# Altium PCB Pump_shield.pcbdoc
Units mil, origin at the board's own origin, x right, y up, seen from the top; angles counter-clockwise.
Board outline 6300 x 3950 mil, 3 copper layers (Top Layer, Mid-Layer 1, Bottom Layer); 32 components, 23 nets, 98 pads, 0 vias.
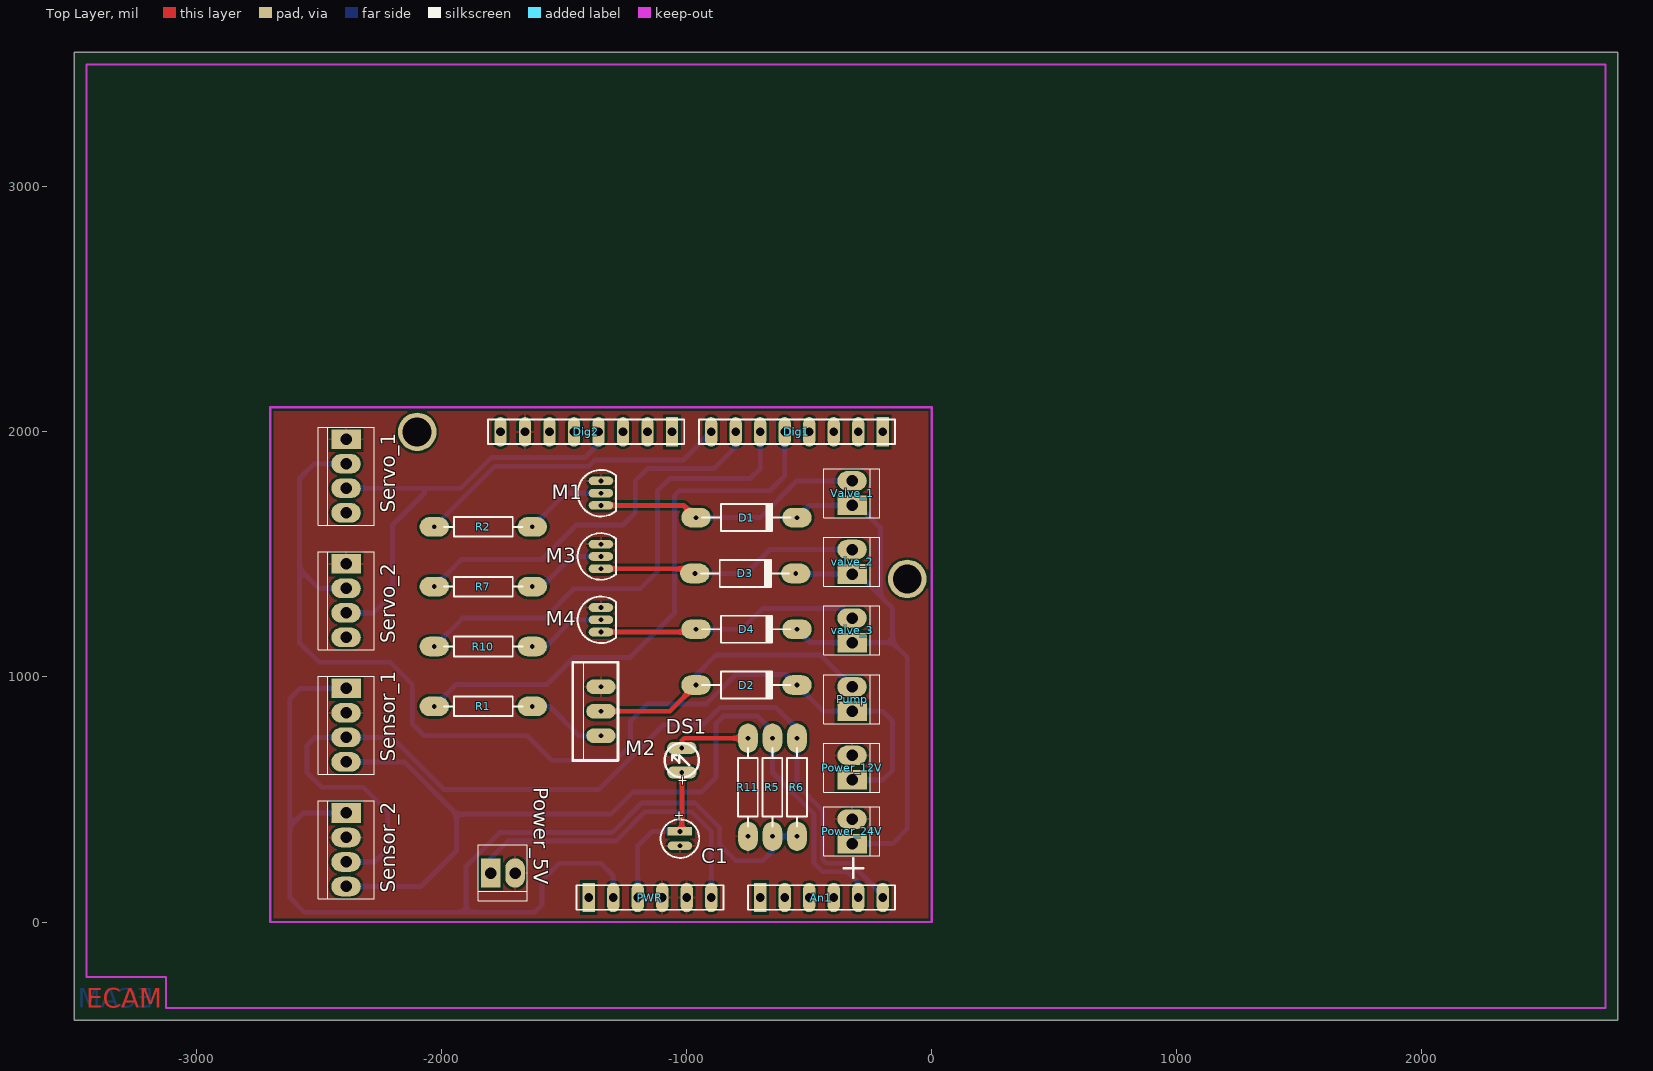
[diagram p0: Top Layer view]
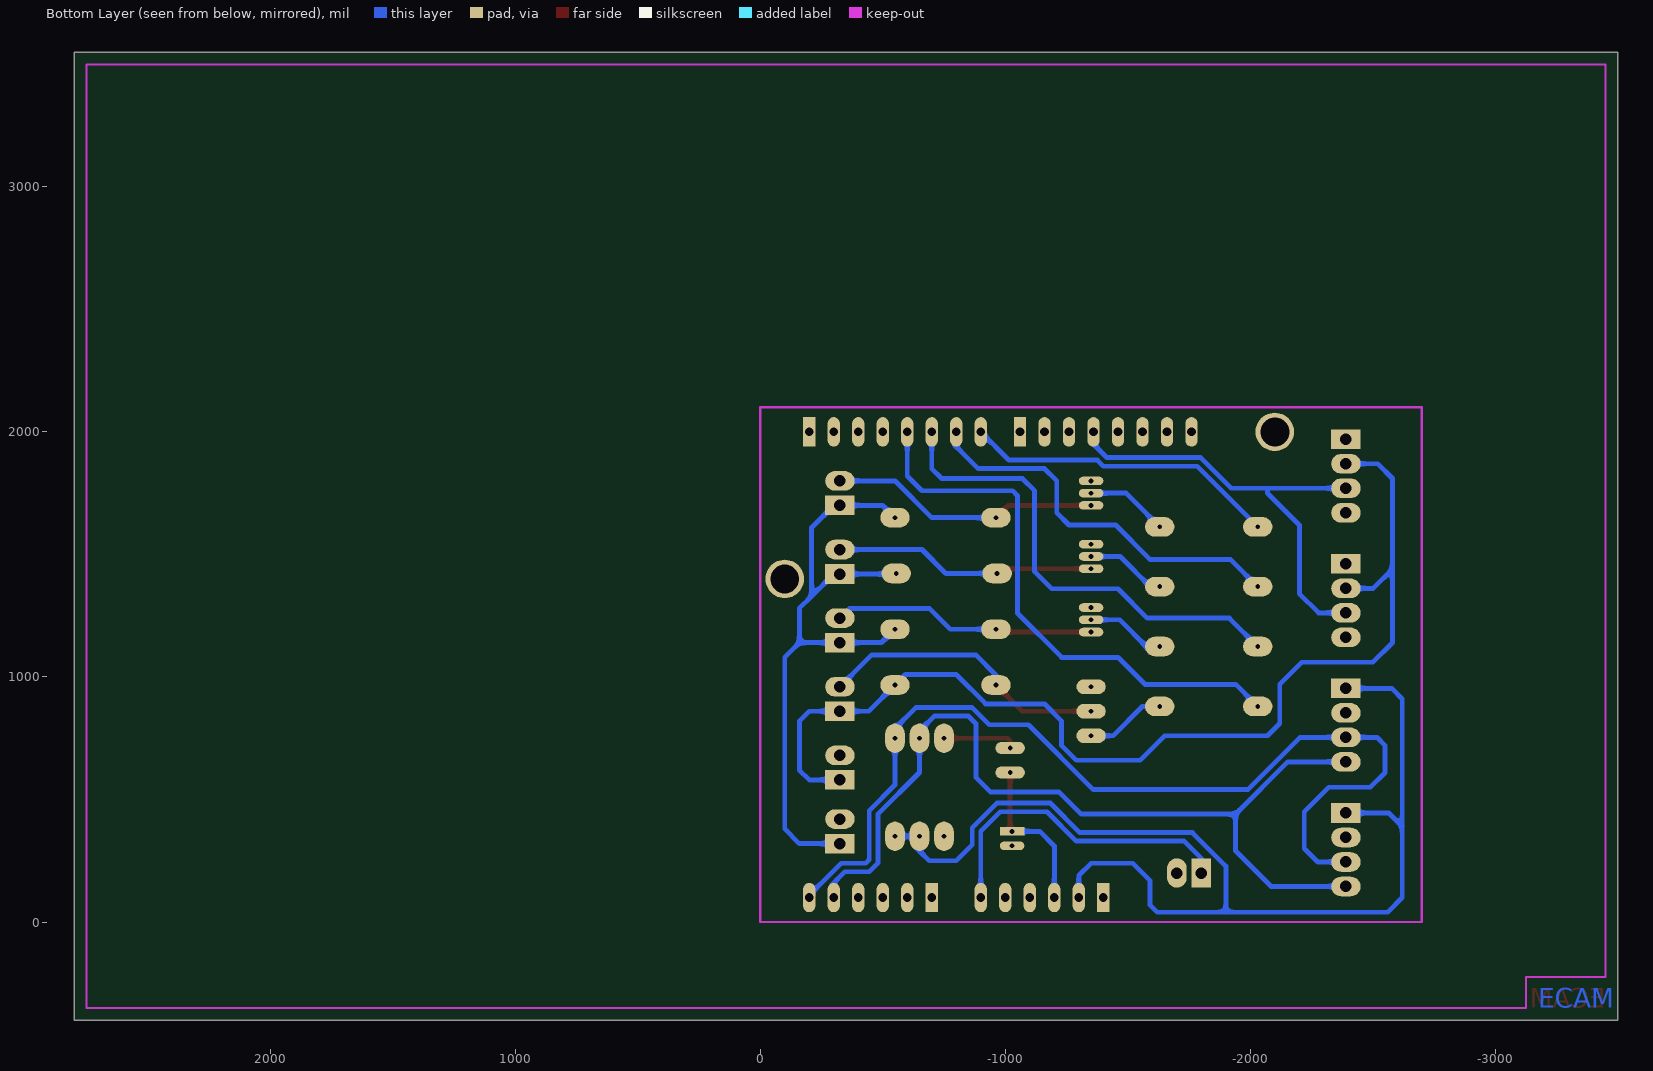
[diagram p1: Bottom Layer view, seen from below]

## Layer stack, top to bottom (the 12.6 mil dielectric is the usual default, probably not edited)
Top Solder: solder mask 0.4, Solder Resist, Dk 3.5
Top Layer: signal copper 1.4
Dielectric1: core 12.6, FR-4, Dk 4.8
Mid-Layer 1: signal copper 1.4
Dielectric2: dielectric 12.6, FR-4, Dk 4.8
Bottom Layer: signal copper 1.4
Bottom Solder: solder mask 0.4, Solder Resist, Dk 3.5

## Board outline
-3500,-400 -3500,3550 2800,3550 2800,-400

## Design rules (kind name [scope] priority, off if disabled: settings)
Clearance "Clearance T DIP" [(IsTrack) vs (IsPad AND( HasFootprint('DIP*')))] p1: gap=10 ignorepadtopadclearanceinfootprint=FALSE
Clearance "Clearance PT" [(isTrack) vs (isPad)] p2: gap=10 ignorepadtopadclearanceinfootprint=FALSE
Clearance "Clearance TT" [(isTrack) vs (isTrack)] p3: gap=15 ignorepadtopadclearanceinfootprint=FALSE
Clearance "Clearance PP" [(IsPad) vs (IsPad)] p4: gap=10 ignorepadtopadclearanceinfootprint=FALSE
Clearance [All] p5: gap=10 ignorepadtopadclearanceinfootprint=FALSE
FabricationTestPointUsage TestPointUsage [All] p1: valid=0 allowmultiple=FALSE
FabricationTestpoint Testpoint [All] p1: side=3 testpointundercomponent=TRUE minsize=40 maxsize=100 preferedsize=60 minholesize=0 maxholesize=40 preferedholesize=32 testpointgrid=1 allowsidetop=TRUE allowsidebottom=TRUE usegrid=TRUE gridtolerance=0.01
HoleSize [All] p1: absolutevalues=TRUE maxlimit=21.65 minlimit=17.72 maxpercent=80.000 minpercent=20.000
PlaneClearance [All] p1: clearance=10
PlaneConnect [All] p1: planeconnectstyle=Relief reliefexpansion=10 reliefentries=4 reliefconductorwidth=10 reliefairgap=5
PolygonConnect [All] p1: connectstyle=Relief reliefconductorwidth=10 reliefentries=4 polygonreliefangle="90 Angle" airgapwidth=10
RoutingCorners [All] p1: cornerstyle=45-Degree minsetback=100 maxsetback=1000
RoutingLayers [All] p1: top layer_v5=TRUE mid layer 1_v5=FALSE bottom layer_v5=TRUE
RoutingVias "ECAM Vias" [All] p1: holewidth=19.68 width=80 viastyle="Through Hole" minholewidth=17.72 minwidth=60 maxholewidth=21.65 maxwidth=120
SolderMaskExpansion [All] p1: expansion=4
UnpouredPolygon [InNet('3V3')] p1:
Width Width_GND [InNet('GND')] p1: maxlimit=40 minlimit=10 preferedwidth=20
Width Width_VCC [InNet('VCC')] p2: maxlimit=40 minlimit=10 preferedwidth=20
Width [All] p3: maxlimit=40 minlimit=10 preferedwidth=20
22 further rules are at their usual default settings.

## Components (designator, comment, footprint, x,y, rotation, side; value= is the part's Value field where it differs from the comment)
An1 "Header 6" HDR1X6 -700,100 r0 top
C1 "Cond pol radial" CAPPR1.5-4x5 -1027.68,370 r270 top
D1 "Diode" DIO10.46-5.3x2.8 -961.81,1650 r0 top
D2 "Diode" DIO10.46-5.3x2.8 -961.81,967.19 r0 top
D3 "Diode" DIO10.46-5.3x2.8 -966.81,1422.4 r0 top
D4 "Diode" DIO10.46-5.3x2.8 -961.81,1194.79 r0 top
Dig1 "Header 8" HDR1X8 -200,2000 r180 top
Dig2 "Header 8" HDR1X8 -1060,2000 r180 top
DS1 "LED" "LED 0.1" -1020,610 r90 top
M1 "MOSFET-N" TO-92 -1350,1800 r0 top value=NMOS
M2 "MOSFET-N" "TO-220 V" -1350,760 r90 top value=NMOS
M3 "MOSFET-N" TO-92 -1350,1541.67 r0 top value=NMOS
M4 "MOSFET-N" TO-92 -1350,1283.33 r0 top value=NMOS
Power_5V "Molex_2" Header_2Ecam -1650,200.79 r180 top
Power_12V "Molex_2" Header_2Ecam -325.79,730 r270 top
Power_24V "Molex_2" Header_2Ecam -325.79,470 r270 top
Pump "Molex_2" Header_2Ecam -325.79,1010 r270 top
PWR "Header 6" HDR1X6 -1400,100 r0 top
R1 "Résistance" AXIAL-0.4 -2030,880 r0 top
R2 "Résistance" AXIAL-0.4 -2030,1612.81 r0 top
R5 "Résistance" AXIAL-0.4 -650,750 r270 top
R6 "Résistance" AXIAL-0.4 -550,750 r270 top
R7 "Résistance" AXIAL-0.4 -2030,1368.54 r0 top
R10 "Résistance" AXIAL-0.4 -2030,1124.27 r0 top
R11 "Résistance" AXIAL-0.4 -750,350 r90 top
Sensor_1 "Molex_4" Header4_ecam -2389.21,603.33 r90 top
Sensor_2 "Molex_4" Header4_ecam -2389.21,95 r90 top
Servo_1 "Molex_4" Header4_ecam -2389.21,1620 r90 top
Servo_2 "Molex_4" Header4_ecam -2389.21,1111.67 r90 top
Valve_1 "Molex_2" Header_2Ecam -325.79,1850 r270 top
valve_2 "Molex_2" Header_2Ecam -325.79,1570 r270 top
valve_3 "Molex_2" Header_2Ecam -325.79,1290 r270 top

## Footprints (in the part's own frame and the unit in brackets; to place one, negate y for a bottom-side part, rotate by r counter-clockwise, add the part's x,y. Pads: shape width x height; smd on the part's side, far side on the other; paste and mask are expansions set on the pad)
AXIAL-0.4 [mil] "Resistor; 2 Leads"
  oval 120x80 hole 19.68: 1(0,0) 2(400,0)
  silkscreen extent 40,-40 360,40
CAPPR1.5-4x5 [mm] "Capacitor, Electrolytic, Radial; Body 4 x 5 mm (Dia.xH typ); Pin Spacing 1.5 mm (typ)"
  rect 0.889x2.54 hole 0.5: 1(0,0)
  oval 0.889x2.54 hole 0.5: 2(1.5,0)
  silkscreen extent -1.25,-2 2.75,2
DIO10.46-5.3x2.8 [mil] "Diode, Axial; Body 5.2 x 2.7 mm (LxDia. max), Lead Dia. 0.86 mm (max)"
  oval 120x80 hole 19.68: 1(0,0) 2(411.81,0)
  silkscreen extent 25,-55 385,55
HDR1X6 [mil] "Connector; Header; 6 Position"
  rect 50x120 hole 35.43: 1(0,0)
  oval 50x120 hole 35.43: 2(100,0) 3(200,0) 4(300,0) 5(400,0) 6(500,0)
  silkscreen extent -50,-50 550,50
HDR1X8 [mil] "Connector; Header; 8 Position"
  rect 50x120 hole 35.43: 1(0,0)
  oval 50x120 hole 35.43: 2(100,0) 3(200,0) 4(300,0) 5(400,0) 6(500,0) 7(600,0) 8(700,0)
  silkscreen extent -50,-50 750,50
Header4_ecam [mil]
  rect 80x120 hole 46.85: 1(350,0.79)
  oval 80x120 hole 46.85: 2(250,0.79) 3(150,0.79) 4(50,0.79)
  silkscreen extent 0,-114 400,114
Header_2Ecam [mil]
  rect 80x120 hole 46.85: 1(150,0.79)
  oval 80x120 hole 46.85: 2(50,0.79)
  silkscreen extent 0,-114 200,114
"LED 0.1" [mil] "Led Verticale"
  oval 50x120 hole 19.68: 1(0,0) 2(100,0)
  silkscreen extent -20,-70 120,70
TO-92 [mil] "TO, Flat Index; 3 In-Line, Axial Leads; Body Dia. 4.6mm; Leads 0.48 x 0.43 mm (max) NOT ECAM RULES"
  oval 100x35 hole 19.68: D(0,-100) G(0,-50) S(0,0)
  silkscreen extent -95,-145 61,45
"TO-220 V" [mil] "TO-220 Vertical"
  oval 60x120 hole 19.68: D(100,0) G(0,0) S(200,0)
  silkscreen extent -100,-70 300,115

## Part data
An1 PWR: "Header, 6-Pin"
C1: "Condensateur polatisé"
Dig1 Dig2: "Header, 8-Pin"
DS1: Color=Rouge
M1 M2 M3 M4: "MOSFET"
Power_5V Power_12V Power_24V Pump Valve_1 valve_2 valve_3: "Header, 2-pin"
R1 R2 R5 R6 R7 R10 R11: "Résistance standard"
Sensor_1 Sensor_2 Servo_1 Servo_2: "Header, 4-Pin"

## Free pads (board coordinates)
  round 157.48 hole 118.11: M(-2100,2000) M(-100,1400)

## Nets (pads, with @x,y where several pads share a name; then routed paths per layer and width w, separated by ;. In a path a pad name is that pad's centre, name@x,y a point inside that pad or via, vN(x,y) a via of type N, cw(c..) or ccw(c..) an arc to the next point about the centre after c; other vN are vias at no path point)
3V3: PWR.2 R5.2 R6.2 Sensor_1.1 Sensor_2.1 | length 4767
  Bottom Layer w20: Sensor_2.1 -2565,445 -2620,390 ; Sensor_1.1 -2576.67,953.33 -2620,910 -2620,390 ; PWR.2 -1300,190 -1350,240 -1520,240 -1590,170 -1590,70 -1620,40 -1900,40 ; R6.2 R5.2 -650,290 -690,250 -800,250 -865,315 -865,384.5 -965.5,485 -1184.5,485 -1304.5,365 -1763.28,365 -1900,228.28 -1900,40 ; -2620,390 -2620,100 -2560,40 -1900,40
+5: Power_5V.1 PWR.6 | length 1341.8
  Bottom Layer w20: Power_5V.1 -1800,260 -1730,330 -1290,330 -1170,450 -980,450 -900,370 PWR.6
+12: D2.2 Power_12V.1 Pump.1 Servo_1.2 Servo_2.2 | length 4483.7
  Bottom Layer w20: Servo_2.2 -2501.67,1361.67 -2580,1440 ; Servo_1.2 -2520,1870 -2580,1810 -2580,1440 ; Power_12V.1 -200,580 -160,620 -160,820 -200,860 Pump.1 -442.81,860 D2.2 -592.81,1010 -800,1010 -920,890 -1160,890 -1230,820 -1230,720 -1290,660 -1550,660 -1650,760 -2070,760 -2120,810 -2120,970 -2210,1060 -2500,1060 -2580,1140 -2580,1440
+24: D1.2 D3.2 D4.2 Power_24V.1 Valve_1.1 valve_2.1 valve_3.1 | length 2719.4
  Bottom Layer w20: D3.2 -552.6,1420 valve_2.1 -300,1420 -210,1330 ; D4.2 -495.21,1140 valve_3.1 -160,1140 ; D1.2 -500,1700 Valve_1.1 -300,1700 -210,1610 -210,1330 ; Power_24V.1 -160,320 -100,380 -100,1080 -160,1140 ; -210,1330 -160,1280 -160,1140
GND: C1.2 Dig2.7 M1.S M2.S M3.S M4.S Power_5V.2 Power_12V.2 Power_24V.2 PWR.4 PWR.5 R11.1 Sensor_1.2 Sensor_2.2 Servo_1.1 Servo_2.1
NetDS1_2: DS1.2 R11.2 | length 304.1
  Top Layer w20: DS1.2 -1020,740 -1010,750 R11.2
NetM1_G: M1.G R2.2 | length 336.8
  Bottom Layer w20: R2.2 -1492.81,1750 M1.G
NetM2_G: M2.G R1.2 | length 329.7
  Bottom Layer w20: R1.2 -1560,880 -1440,760 M2.G
NetM3_G: M3.G R7.2 | length 331
  Bottom Layer w20: R7.2 -1591.46,1368.54 -1468.33,1491.67 M3.G
NetM4_G: M4.G R10.2 | length 325.2
  Bottom Layer w20: R10.2 -1575.73,1124.27 -1466.67,1233.33 M4.G
Pump: Dig1.5 R1.1 | length 2280.5
  Bottom Layer w20: R1.1 -1940,970 -1570,970 -1460,1080 -1230,1080 -1050,1260 -1050,1740 -1030,1760 -660,1760 -600,1820 Dig1.5
RX_moteur: Dig2.3
SCL_Sensor: An1.6 R6.1 Sensor_1.3 Sensor_2.3 | length 4018.5
  Bottom Layer w20: Sensor_2.3 -2275,245 -2220,300 -2220,450 -2320,550 -2490,550 -2550,610 -2550,720 -2516.67,753.33 Sensor_1.3 -2203.33,753.33 -1990,540 -1359.5,540 -1094.5,805 -934.5,805 -864.5,875 -635,875 -550,790 R6.1 -550,559.5 -445,454.5 -445,255 -430,240 -330.5,240 -200,109.5 An1.6
SDA_Sensor: An1.5 R5.1 Sensor_1.4 Sensor_2.4 | length 3691.6
  Bottom Layer w20: Sensor_2.4 -2085,145 -1939.5,290.5 -1939.5,440 ; Sensor_1.4 -2152.83,653.33 -1939.5,440 ; An1.5 -300,160 -345,205 -445,205 -480,240 -480,440 -650,610 R5.1 -660,760 -660,790 -710,840 -850,840 -880,810 -880,590 -940,530 -1220,530 -1310,440 -1939.5,440
T_1: D1.1 M1.D Valve_1.2 | length 1107.8
  Top Layer w20: M1.D -1011.81,1700 D1.1
  Bottom Layer w20: D1.1 -700,1650 -550,1800 Valve_1.2
T_2: D3.1 M3.D valve_2.2 | length 1073.4
  Top Layer w20: M3.D -986.08,1441.67 D3.1
  Bottom Layer w20: D3.1 -757.6,1422.4 -660,1520 valve_2.2
T_3: D4.1 M4.D valve_3.2 | length 1081.6
  Top Layer w20: M4.D -973.27,1183.33 D4.1
  Bottom Layer w20: D4.1 -775.21,1194.79 -690,1280 -365,1280 valve_3.2
T_4: D2.1 M2.D Pump.2 | length 1198.1
  Top Layer w20: M2.D -1069,860 D2.1
  Bottom Layer w20: D2.1 -961.81,1008.19 -880,1090 -455,1090 Pump.2
TX_moteur: Dig2.4 Servo_1.3 Servo_2.3 | length 1860.9
  Bottom Layer w20: Servo_2.3 -2278.33,1261.67 -2200,1340 -2200,1620 -2070,1750 -2070,1770 ; Servo_1.3 -2070,1770 ; Dig2.4 -1360,1950 -1415,1895 -1797.31,1895 -1922.31,1770 -2070,1770
Val_1: Dig1.8 R2.1 | length 1290.4
  Bottom Layer w20: R2.1 -1782.81,1860 -1400.5,1860 -1375.5,1885 -1015,1885 Dig1.8
Val_2: Dig1.7 R7.1 | length 1602.9
  Bottom Layer w20: R7.1 -1918.54,1480 -1590,1480 -1450,1620 -1260,1620 -1210,1670 -1210,1800 -1160,1850 -890,1850 -800,1940 Dig1.7
Val_3: Dig1.6 R10.1 | length 1973.9
  Bottom Layer w20: R10.1 -1914.27,1240 -1580,1240 -1460,1360 -1190,1360 -1120,1430 -1120,1760 -1070,1810 -740,1810 -700,1850 Dig1.6
VCC: C1.1 DS1.1 PWR.3 | length 661.2
  Top Layer w20: C1.1 -1020,377.68 DS1.1
  Bottom Layer w20: PWR.3 -1200,310 -1140,370 C1.1 C1.1@-1020,377.68
pads on no net: An1.1 An1.2 An1.3 An1.4 Dig1.1 Dig1.2 Dig1.3 Dig1.4 Dig2.1 Dig2.2 Dig2.5 Dig2.6 Dig2.8 PWR.1 Servo_1.4 Servo_2.4

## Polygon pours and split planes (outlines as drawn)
GND on Top Layer (solid, remove dead copper, pour order 0): -2700,2100 -10,2100 0,2090 0,0 -2700,0

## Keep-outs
Keep-Out Layer:
  lines w8: -3450,-225 -3125,-225 -3125,-350 2750,-350 2750,3500 -3450,3500 -3450,-225
  lines w10: -2700,0 0,0 0,200 0,1450 0,2100 -2700,2100 -2700,0

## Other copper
Top Layer:
  region net GND: -2600,-50
  text "ECAM" at -3450,-350 h78.74
  text ".GTL" at 4264,-1928 h90
Bottom Layer:
  text "ECAM" at -3175,-350 h78.74
  text ".GBL" at 4264,-1928 h90
Multi-Layer:

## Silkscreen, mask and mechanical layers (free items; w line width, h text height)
Top Overlay:
  lines w10: -360,220 -280,220 ; -320,180 -320,220 -320,260
  text ".GTO" at 4264,-1928 h90
Top Paste:
  text ".GTP" at 4264,-1928 h90
Bottom Paste:
  text ".GBP" at 4264,-1928 h90
Top Solder:
  text ".GTS" at 4264,-1928 h90
Bottom Solder:
  text ".GBS" at 4264,-1928 h90
Mechanical 1:
  the board outline again, w7.87
Mechanical 16:
  circle w3.94: c3170,-1915 r55.12
  lines w5: -5675,-625 -5475,-625 ; -5675,1275 -5475,1275 ; -5675,3175 -5475,3175 ; -3195,-2525 -3195,-2325 ; -3195,4875 -3195,5075 ; -320,-2525 -320,-2325 ; -320,4875 -320,5075 ; 315,-2025 4815,-2025 ; 315,-1725 4815,-1725 ; 315,-1425 1815,-1425 ; 1815,-2325 1815,-1725 1815,-1125 ; 2555,-2525 2555,-2325 ; 2555,4875 2555,5075 ; 3915,-2325 3915,-1725 ; 4815,-635 5015,-635 ; 4815,1265 5015,1265 ; 4815,3165 5015,3165 ; 315,-2325 -1085,-2325 -1085,-1125 315,-1125 ; 315,-2325 4815,-2325 ; 315,-2325 315,-1125 ; 315,-1125 1815,-1125 ; 1815,-1125 4815,-1125 4815,-2325 ; 4815,-2325 4815,4875 -5475,4875 -5475,-2325 4815,-2325 ; -5675,-2525 -5675,5075 5015,5075 5015,-2525 -5675,-2525
  text "1" at -4643,4940 h70
  text "2" at -1783,4940 h70
  text "3" at 1097,4940 h70
  text "4" at 3967,4940 h70
  text "A" at -5600,4034 h70
  text "A" at 4890,4024 h70
  text "B" at -5600,2142 h70
  text "B" at 4890,2132 h70
  text "C" at -5600,232 h70
  text "C" at 4890,222 h70
  text "Concepteur du circuit :" at 365,-1225 h45
  text "TITRE :" at 1865,-1225 h45
  text "Stilmant.J" at 740,-1375 h80
  text "Shield Arduino for Festo" at 2125,-1495 h100
  text "Concepteur du PCB :" at 365,-1520 h45
  text "ECAM" at -850,-1535 h240
  text "D" at -5600,-1658 h70
  text "D" at 4890,-1668 h70
  text "Stilmant.J" at 735,-1680 h80
  text "Prom. de l'Alma 50" at -780,-1805 h60
  text "Date :" at 365,-1825 h45
  text "PART NO.:" at 1865,-1825 h45
  text "Layer :" at 3965,-1825 h45
  text ".Print_Date" at 755,-1860 h70
  text "1" at 1870,-1945 h60
  text "C" at 3145,-1945 h60
  text "ECAM" at 3251,-1960 h100
  text ".Print_Time" at 760,-1990 h70
  text "1200 Bruxelles" at -780,-2025 h60
  text "Nom du fichier :" at 365,-2125 h45
  text "DWG NO:" at 1865,-2125 h45
  text ".Print_Scale" at 4125,-2205 h40
  text ".Printout_Name" at 2015,-2240 h60
  text ".Pcb_File_Name_No_Path" at 415,-2245 h70
  text "1" at -4643,-2460 h70
  text "2" at -1783,-2460 h70
  text "3" at 1097,-2460 h70
  text "4" at 3967,-2460 h70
